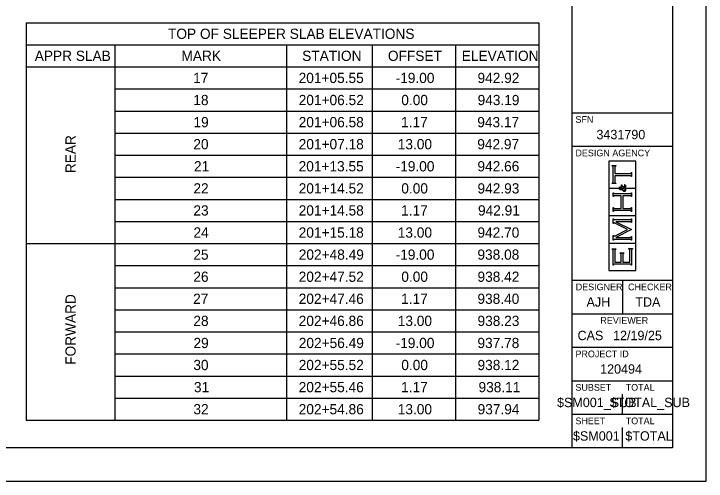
# Model space of a CAD drawing. Extents: x 0 to 34, y 0 to 22.
# Drawn here: x 23.67 to 34, y 0 to 6.98 of the extents above; entities that cross this region are included whole.
import ezdxf

# ---------------------------------------------------------------- set-up
doc = ezdxf.new("R2010")
doc.units = 0
for name, color, linetype in [('BR_P_Gen_Text', 7, 'Continuous'), ('SH_Border', 7, 'Continuous'), ('SH_Cut_Line', 7, 'Continuous'), ('SH_Data', 7, 'Continuous')]:
    doc.layers.add(name, color=color, linetype=linetype)

msp = doc.modelspace()

# ---------------------------------------------------------------- linework, layer by layer
at = {"layer": 'BR_P_Gen_Text'}
for p, q in [((23.857, 6.844), (31.504, 6.844)), ((23.857, 6.844), (23.857, 0.91)), ((31.504, 6.844), (31.504, 0.91)), ((23.857, 6.515), (31.504, 6.515)), ((25.176, 6.515), (25.176, 0.91)), ((27.738, 6.515), (27.738, 0.91)), ((29.019, 6.515), (29.019, 0.91)), ((30.261, 6.515), (30.261, 0.91)), ((23.857, 6.185), (31.504, 6.185)), ((25.176, 5.855), (31.504, 5.855)), ((25.176, 5.526), (31.504, 5.526)), ((25.176, 5.196), (31.504, 5.196)), ((25.176, 4.866), (31.504, 4.866)), ((25.176, 4.537), (31.504, 4.537)), ((25.176, 4.207), (31.504, 4.207)), ((25.176, 3.877), (31.504, 3.877)), ((23.857, 3.547), (31.504, 3.547)), ((25.176, 3.218), (31.504, 3.218)), ((25.176, 2.888), (31.504, 2.888)), ((25.176, 2.558), (31.504, 2.558)), ((25.176, 2.229), (31.504, 2.229)), ((25.176, 1.899), (31.504, 1.899)), ((25.176, 1.569), (31.504, 1.569)), ((25.176, 1.239), (31.504, 1.239)), ((23.857, 0.91), (31.504, 0.91))]:
    msp.add_line(p, q, dxfattribs=at)
at = {"layer": 'SH_Border'}
for p, q in [((32, 0.5), (32, 21.5)), ((32, 5.5), (33.5, 5.5)), ((32, 5), (33.5, 5)), ((32, 3), (33.5, 3)), ((32.75, 3), (32.75, 2.5)), ((32, 2.5), (33.5, 2.5)), ((32, 2), (33.5, 2)), ((32, 1.5), (33.5, 1.5)), ((32, 1), (33.5, 1))]:
    msp.add_line(p, q, dxfattribs=at)
msp.add_lwpolyline([(1.5, 21.5), (33.5, 21.5), (33.5, 0.5), (1.5, 0.5)], close=True, dxfattribs=at)
at = {"layer": 'SH_Cut_Line'}
msp.add_lwpolyline([(0, 0), (34, 0), (34, 22), (0, 22)], close=True, dxfattribs=at)
at = {"layer": 'SH_Data'}
for p, q in [((32.952, 4.779), (32.547, 4.779)), ((32.547, 4.779), (32.547, 4.375)), ((32.952, 4.375), (32.952, 4.779)), ((32.598, 4.704), (32.598, 4.711)), ((32.598, 4.711), (32.65, 4.711)), ((32.603, 4.703), (32.598, 4.704)), ((32.606, 4.701), (32.603, 4.703)), ((32.608, 4.699), (32.606, 4.701)), ((32.61, 4.696), (32.608, 4.699)), ((32.611, 4.692), (32.61, 4.696)), ((32.611, 4.687), (32.611, 4.692)), ((32.611, 4.468), (32.611, 4.687)), ((32.638, 4.696), (32.637, 4.692)), ((32.637, 4.692), (32.637, 4.687)), ((32.637, 4.687), (32.637, 4.593)), ((32.64, 4.699), (32.638, 4.696)), ((32.642, 4.701), (32.64, 4.699)), ((32.645, 4.703), (32.642, 4.701)), ((32.65, 4.704), (32.645, 4.703)), ((32.65, 4.711), (32.65, 4.704)), ((32.637, 4.593), (32.864, 4.593)), ((32.864, 4.561), (32.637, 4.561)), ((32.637, 4.561), (32.637, 4.468)), ((32.864, 4.593), (32.869, 4.593)), ((32.87, 4.561), (32.864, 4.561)), ((32.869, 4.593), (32.873, 4.594)), ((32.874, 4.56), (32.87, 4.561)), ((32.873, 4.594), (32.876, 4.596)), ((32.876, 4.559), (32.874, 4.56)), ((32.876, 4.596), (32.878, 4.597)), ((32.878, 4.557), (32.876, 4.559)), ((32.878, 4.597), (32.88, 4.601)), ((32.88, 4.553), (32.878, 4.557)), ((32.88, 4.601), (32.881, 4.606)), ((32.881, 4.548), (32.88, 4.553)), ((32.881, 4.606), (32.888, 4.606)), ((32.888, 4.548), (32.881, 4.548)), ((32.888, 4.606), (32.888, 4.548)), ((32.598, 4.45), (32.603, 4.451)), ((32.598, 4.444), (32.598, 4.45)), ((32.65, 4.444), (32.598, 4.444)), ((32.603, 4.451), (32.606, 4.453)), ((32.606, 4.453), (32.608, 4.455)), ((32.608, 4.455), (32.61, 4.458)), ((32.61, 4.458), (32.611, 4.462)), ((32.611, 4.462), (32.611, 4.468)), ((32.637, 4.468), (32.637, 4.462)), ((32.637, 4.462), (32.638, 4.458)), ((32.638, 4.458), (32.64, 4.455)), ((32.64, 4.455), (32.642, 4.453)), ((32.642, 4.453), (32.645, 4.451)), ((32.645, 4.451), (32.65, 4.45)), ((32.65, 4.45), (32.65, 4.444)), ((32.547, 4.375), (32.696, 4.375)), ((32.696, 4.369), (32.547, 4.369)), ((32.547, 4.369), (32.547, 3.965)), ((32.696, 4.375), (32.696, 4.369)), ((32.703, 4.379), (32.705, 4.383)), ((32.703, 4.373), (32.703, 4.379)), ((32.703, 4.368), (32.703, 4.373)), ((32.705, 4.363), (32.703, 4.368)), ((32.705, 4.383), (32.708, 4.387)), ((32.708, 4.358), (32.705, 4.363)), ((32.708, 4.387), (32.711, 4.39)), ((32.709, 4.379), (32.708, 4.376)), ((32.708, 4.376), (32.708, 4.373)), ((32.708, 4.373), (32.708, 4.369)), ((32.708, 4.369), (32.71, 4.366)), ((32.712, 4.353), (32.708, 4.358)), ((32.712, 4.381), (32.709, 4.379)), ((32.71, 4.366), (32.712, 4.364)), ((32.711, 4.39), (32.715, 4.392)), ((32.714, 4.383), (32.712, 4.381)), ((32.712, 4.364), (32.715, 4.362)), ((32.718, 4.35), (32.712, 4.353)), ((32.716, 4.384), (32.714, 4.383)), ((32.715, 4.392), (32.72, 4.392)), ((32.715, 4.362), (32.718, 4.361)), ((32.72, 4.384), (32.716, 4.384)), ((32.718, 4.361), (32.721, 4.361)), ((32.726, 4.35), (32.718, 4.35)), ((32.72, 4.392), (32.725, 4.392)), ((32.724, 4.384), (32.72, 4.384)), ((32.721, 4.361), (32.723, 4.361)), ((32.723, 4.361), (32.725, 4.362)), ((32.728, 4.382), (32.724, 4.384)), ((32.725, 4.392), (32.729, 4.39)), ((32.725, 4.362), (32.728, 4.362)), ((32.729, 4.35), (32.726, 4.35)), ((32.731, 4.38), (32.728, 4.382)), ((32.728, 4.362), (32.731, 4.363)), ((32.729, 4.39), (32.732, 4.387)), ((32.731, 4.35), (32.729, 4.35)), ((32.734, 4.377), (32.731, 4.38)), ((32.731, 4.363), (32.735, 4.365)), ((32.734, 4.351), (32.731, 4.35)), ((32.732, 4.387), (32.736, 4.383)), ((32.737, 4.372), (32.734, 4.377)), ((32.737, 4.352), (32.734, 4.351)), ((32.735, 4.365), (32.74, 4.367)), ((32.736, 4.383), (32.74, 4.378)), ((32.74, 4.367), (32.737, 4.372)), ((32.741, 4.353), (32.737, 4.352)), ((32.738, 4.393), (32.738, 4.422)), ((32.738, 4.422), (32.741, 4.422)), ((32.741, 4.393), (32.738, 4.393)), ((32.74, 4.378), (32.744, 4.369)), ((32.741, 4.422), (32.741, 4.418)), ((32.741, 4.418), (32.742, 4.415)), ((32.742, 4.396), (32.741, 4.395)), ((32.741, 4.395), (32.741, 4.393)), ((32.746, 4.355), (32.741, 4.353)), ((32.742, 4.415), (32.743, 4.413)), ((32.743, 4.397), (32.742, 4.396)), ((32.743, 4.413), (32.745, 4.411)), ((32.745, 4.399), (32.743, 4.397)), ((32.744, 4.369), (32.754, 4.375)), ((32.745, 4.411), (32.749, 4.408)), ((32.746, 4.399), (32.745, 4.399)), ((32.748, 4.399), (32.746, 4.399)), ((32.752, 4.344), (32.746, 4.355)), ((32.755, 4.399), (32.748, 4.399)), ((32.749, 4.408), (32.756, 4.404)), ((32.756, 4.36), (32.751, 4.357)), ((32.751, 4.357), (32.754, 4.352)), ((32.757, 4.337), (32.752, 4.344)), ((32.754, 4.375), (32.764, 4.381)), ((32.754, 4.352), (32.757, 4.348)), ((32.763, 4.395), (32.755, 4.399)), ((32.756, 4.404), (32.763, 4.4)), ((32.761, 4.363), (32.756, 4.36)), ((32.757, 4.348), (32.761, 4.345)), ((32.764, 4.365), (32.761, 4.363)), ((32.761, 4.345), (32.765, 4.343)), ((32.763, 4.4), (32.77, 4.396)), ((32.772, 4.387), (32.763, 4.395)), ((32.764, 4.381), (32.772, 4.387)), ((32.768, 4.367), (32.764, 4.365)), ((32.765, 4.343), (32.769, 4.341)), ((32.774, 4.372), (32.768, 4.367)), ((32.769, 4.341), (32.773, 4.341)), ((32.77, 4.396), (32.776, 4.391)), ((32.773, 4.341), (32.778, 4.341)), ((32.782, 4.378), (32.774, 4.372)), ((32.776, 4.391), (32.781, 4.395)), ((32.778, 4.341), (32.782, 4.343)), ((32.779, 4.423), (32.781, 4.426)), ((32.782, 4.422), (32.779, 4.423)), ((32.781, 4.426), (32.787, 4.424)), ((32.781, 4.395), (32.784, 4.398)), ((32.785, 4.421), (32.782, 4.422)), ((32.786, 4.373), (32.782, 4.378)), ((32.782, 4.343), (32.786, 4.346)), ((32.784, 4.398), (32.786, 4.401)), ((32.786, 4.419), (32.785, 4.421)), ((32.788, 4.417), (32.786, 4.419)), ((32.786, 4.401), (32.788, 4.404)), ((32.791, 4.386), (32.786, 4.381)), ((32.786, 4.381), (32.791, 4.376)), ((32.788, 4.369), (32.786, 4.373)), ((32.786, 4.346), (32.789, 4.349)), ((32.787, 4.424), (32.792, 4.421)), ((32.789, 4.414), (32.788, 4.417)), ((32.788, 4.404), (32.789, 4.408)), ((32.79, 4.367), (32.788, 4.369)), ((32.789, 4.411), (32.789, 4.414)), ((32.789, 4.408), (32.789, 4.411)), ((32.789, 4.349), (32.791, 4.353)), ((32.791, 4.364), (32.79, 4.367)), ((32.794, 4.39), (32.791, 4.386)), ((32.791, 4.376), (32.795, 4.37)), ((32.791, 4.361), (32.791, 4.364)), ((32.791, 4.359), (32.791, 4.361)), ((32.791, 4.353), (32.791, 4.359)), ((32.792, 4.421), (32.795, 4.418)), ((32.796, 4.394), (32.794, 4.39)), ((32.795, 4.418), (32.798, 4.414)), ((32.795, 4.37), (32.797, 4.366)), ((32.798, 4.397), (32.796, 4.394)), ((32.797, 4.366), (32.798, 4.361)), ((32.799, 4.344), (32.797, 4.338)), ((32.798, 4.414), (32.799, 4.41)), ((32.799, 4.401), (32.798, 4.397)), ((32.798, 4.361), (32.799, 4.357)), ((32.799, 4.41), (32.799, 4.405)), ((32.799, 4.405), (32.799, 4.401)), ((32.803, 4.369), (32.799, 4.375)), ((32.799, 4.375), (32.952, 4.375)), ((32.799, 4.357), (32.799, 4.352)), ((32.799, 4.352), (32.799, 4.344)), ((32.952, 4.369), (32.803, 4.369)), ((32.952, 3.965), (32.952, 4.369)), ((32.611, 4.249), (32.611, 4.307)), ((32.611, 4.307), (32.617, 4.307)), ((32.617, 4.249), (32.611, 4.249)), ((32.617, 4.307), (32.619, 4.302)), ((32.618, 4.254), (32.617, 4.249)), ((32.62, 4.258), (32.618, 4.254)), ((32.619, 4.302), (32.62, 4.298)), ((32.62, 4.298), (32.623, 4.297)), ((32.623, 4.26), (32.62, 4.258)), ((32.623, 4.297), (32.625, 4.295)), ((32.625, 4.261), (32.623, 4.26)), ((32.625, 4.295), (32.629, 4.294)), ((32.629, 4.262), (32.625, 4.261)), ((32.629, 4.294), (32.635, 4.294)), ((32.635, 4.262), (32.629, 4.262)), ((32.635, 4.294), (32.864, 4.294)), ((32.732, 4.262), (32.635, 4.262)), ((32.732, 4.072), (32.732, 4.262)), ((32.763, 4.333), (32.757, 4.337)), ((32.864, 4.262), (32.759, 4.262)), ((32.759, 4.262), (32.759, 4.072)), ((32.768, 4.329), (32.763, 4.333)), ((32.774, 4.327), (32.768, 4.329)), ((32.779, 4.327), (32.774, 4.327)), ((32.785, 4.327), (32.779, 4.327)), ((32.79, 4.329), (32.785, 4.327)), ((32.793, 4.334), (32.79, 4.329)), ((32.797, 4.338), (32.793, 4.334)), ((32.864, 4.294), (32.869, 4.294)), ((32.87, 4.262), (32.864, 4.262)), ((32.869, 4.294), (32.873, 4.295)), ((32.874, 4.261), (32.87, 4.262)), ((32.873, 4.295), (32.876, 4.297)), ((32.876, 4.26), (32.874, 4.261)), ((32.876, 4.297), (32.878, 4.298)), ((32.878, 4.258), (32.876, 4.26)), ((32.878, 4.298), (32.88, 4.302)), ((32.88, 4.254), (32.878, 4.258)), ((32.88, 4.302), (32.881, 4.307)), ((32.881, 4.249), (32.88, 4.254)), ((32.881, 4.307), (32.888, 4.307)), ((32.888, 4.249), (32.881, 4.249)), ((32.888, 4.307), (32.888, 4.249)), ((32.611, 4.027), (32.611, 4.085)), ((32.611, 4.085), (32.617, 4.085)), ((32.617, 4.085), (32.619, 4.08)), ((32.618, 4.032), (32.617, 4.027)), ((32.62, 4.036), (32.618, 4.032)), ((32.619, 4.08), (32.62, 4.076)), ((32.62, 4.076), (32.623, 4.074)), ((32.623, 4.037), (32.62, 4.036)), ((32.623, 4.074), (32.625, 4.073)), ((32.625, 4.039), (32.623, 4.037)), ((32.625, 4.073), (32.629, 4.072)), ((32.629, 4.04), (32.625, 4.039)), ((32.629, 4.072), (32.635, 4.072)), ((32.635, 4.04), (32.629, 4.04)), ((32.635, 4.072), (32.732, 4.072)), ((32.864, 4.04), (32.635, 4.04)), ((32.759, 4.072), (32.864, 4.072)), ((32.864, 4.072), (32.87, 4.072)), ((32.87, 4.04), (32.864, 4.04)), ((32.87, 4.072), (32.874, 4.073)), ((32.874, 4.039), (32.87, 4.04)), ((32.874, 4.073), (32.876, 4.074)), ((32.876, 4.038), (32.874, 4.039)), ((32.876, 4.074), (32.878, 4.076)), ((32.878, 4.036), (32.876, 4.038)), ((32.878, 4.076), (32.88, 4.08)), ((32.88, 4.032), (32.878, 4.036)), ((32.88, 4.08), (32.881, 4.085)), ((32.881, 4.027), (32.88, 4.032)), ((32.881, 4.085), (32.888, 4.085)), ((32.888, 4.085), (32.888, 4.027)), ((32.547, 3.965), (32.952, 3.965)), ((32.952, 3.959), (32.547, 3.959)), ((32.547, 3.959), (32.547, 3.555)), ((32.617, 4.027), (32.611, 4.027)), ((32.75, 4), (32.75, 4)), ((32.888, 4.027), (32.881, 4.027)), ((32.952, 3.555), (32.952, 3.959)), ((32.611, 3.845), (32.611, 3.918)), ((32.611, 3.918), (32.617, 3.918)), ((32.617, 3.845), (32.611, 3.845)), ((32.617, 3.918), (32.619, 3.912)), ((32.62, 3.852), (32.617, 3.845)), ((32.619, 3.912), (32.62, 3.909)), ((32.62, 3.909), (32.623, 3.907)), ((32.622, 3.855), (32.62, 3.852)), ((32.626, 3.855), (32.622, 3.855)), ((32.623, 3.907), (32.625, 3.905)), ((32.625, 3.905), (32.629, 3.905)), ((32.629, 3.855), (32.626, 3.855)), ((32.629, 3.905), (32.635, 3.905)), ((32.633, 3.853), (32.629, 3.855)), ((32.64, 3.85), (32.633, 3.853)), ((32.635, 3.905), (32.864, 3.905)), ((32.825, 3.757), (32.64, 3.85)), ((32.864, 3.873), (32.654, 3.873)), ((32.654, 3.873), (32.888, 3.755)), ((32.864, 3.905), (32.869, 3.905)), ((32.87, 3.873), (32.864, 3.873)), ((32.869, 3.905), (32.873, 3.905)), ((32.874, 3.872), (32.87, 3.873)), ((32.873, 3.905), (32.876, 3.907)), ((32.876, 3.87), (32.874, 3.872)), ((32.876, 3.907), (32.878, 3.909)), ((32.878, 3.869), (32.876, 3.87)), ((32.878, 3.909), (32.88, 3.912)), ((32.88, 3.865), (32.878, 3.869)), ((32.88, 3.912), (32.881, 3.918)), ((32.881, 3.86), (32.88, 3.865)), ((32.881, 3.918), (32.888, 3.918)), ((32.888, 3.86), (32.881, 3.86)), ((32.888, 3.918), (32.888, 3.86)), ((32.641, 3.665), (32.825, 3.757)), ((32.888, 3.755), (32.654, 3.638)), ((32.611, 3.596), (32.611, 3.668)), ((32.611, 3.668), (32.617, 3.668)), ((32.617, 3.668), (32.62, 3.662)), ((32.62, 3.662), (32.622, 3.658)), ((32.622, 3.658), (32.626, 3.658)), ((32.626, 3.658), (32.627, 3.658)), ((32.627, 3.658), (32.633, 3.661)), ((32.633, 3.661), (32.641, 3.665)), ((32.654, 3.638), (32.864, 3.638)), ((32.864, 3.638), (32.869, 3.638)), ((32.869, 3.638), (32.873, 3.639)), ((32.873, 3.639), (32.876, 3.641)), ((32.876, 3.641), (32.878, 3.643)), ((32.878, 3.643), (32.88, 3.646)), ((32.88, 3.646), (32.881, 3.651)), ((32.881, 3.651), (32.888, 3.651)), ((32.888, 3.651), (32.888, 3.596)), ((32.547, 3.555), (32.952, 3.555)), ((32.952, 3.549), (32.547, 3.549)), ((32.547, 3.549), (32.547, 3.145)), ((32.617, 3.596), (32.611, 3.596)), ((32.618, 3.602), (32.617, 3.596)), ((32.62, 3.605), (32.618, 3.602)), ((32.623, 3.607), (32.62, 3.605)), ((32.625, 3.609), (32.623, 3.607)), ((32.629, 3.609), (32.625, 3.609)), ((32.635, 3.609), (32.629, 3.609)), ((32.864, 3.609), (32.635, 3.609)), ((32.87, 3.609), (32.864, 3.609)), ((32.874, 3.609), (32.87, 3.609)), ((32.876, 3.607), (32.874, 3.609)), ((32.878, 3.605), (32.876, 3.607)), ((32.88, 3.602), (32.878, 3.605)), ((32.881, 3.596), (32.88, 3.602)), ((32.888, 3.596), (32.881, 3.596)), ((32.952, 3.145), (32.952, 3.549)), ((32.598, 3.462), (32.598, 3.469)), ((32.598, 3.469), (32.65, 3.469)), ((32.603, 3.461), (32.598, 3.462)), ((32.606, 3.459), (32.603, 3.461)), ((32.608, 3.457), (32.606, 3.459)), ((32.61, 3.455), (32.608, 3.457)), ((32.611, 3.451), (32.61, 3.455)), ((32.611, 3.445), (32.611, 3.451)), ((32.611, 3.225), (32.611, 3.445)), ((32.64, 3.457), (32.638, 3.455)), ((32.638, 3.455), (32.638, 3.451)), ((32.638, 3.451), (32.638, 3.445)), ((32.638, 3.445), (32.638, 3.27)), ((32.642, 3.459), (32.64, 3.457)), ((32.645, 3.461), (32.642, 3.459)), ((32.65, 3.462), (32.645, 3.461)), ((32.65, 3.469), (32.65, 3.462)), ((32.848, 3.465), (32.848, 3.472)), ((32.848, 3.472), (32.901, 3.472)), ((32.853, 3.464), (32.848, 3.465)), ((32.857, 3.462), (32.853, 3.464)), ((32.859, 3.46), (32.857, 3.462)), ((32.86, 3.458), (32.859, 3.46)), ((32.861, 3.453), (32.86, 3.458)), ((32.861, 3.448), (32.861, 3.453)), ((32.861, 3.27), (32.861, 3.448)), ((32.889, 3.457), (32.888, 3.453)), ((32.888, 3.453), (32.888, 3.448)), ((32.888, 3.448), (32.888, 3.225)), ((32.891, 3.46), (32.889, 3.457)), ((32.892, 3.462), (32.891, 3.46)), ((32.896, 3.464), (32.892, 3.462)), ((32.901, 3.465), (32.896, 3.464)), ((32.901, 3.472), (32.901, 3.465)), ((32.719, 3.402), (32.719, 3.408)), ((32.719, 3.408), (32.772, 3.408)), ((32.724, 3.401), (32.719, 3.402)), ((32.728, 3.399), (32.724, 3.401)), ((32.729, 3.396), (32.728, 3.399)), ((32.731, 3.394), (32.729, 3.396)), ((32.732, 3.39), (32.731, 3.394)), ((32.732, 3.384), (32.732, 3.39)), ((32.732, 3.27), (32.732, 3.384)), ((32.76, 3.394), (32.759, 3.39)), ((32.759, 3.39), (32.759, 3.384)), ((32.759, 3.384), (32.759, 3.27)), ((32.761, 3.396), (32.76, 3.394)), ((32.763, 3.399), (32.761, 3.396)), ((32.767, 3.401), (32.763, 3.399)), ((32.772, 3.402), (32.767, 3.401)), ((32.772, 3.408), (32.772, 3.402)), ((32.617, 3.225), (32.611, 3.225)), ((32.619, 3.23), (32.617, 3.225)), ((32.62, 3.234), (32.619, 3.23)), ((32.623, 3.235), (32.62, 3.234)), ((32.625, 3.237), (32.623, 3.235)), ((32.629, 3.238), (32.625, 3.237)), ((32.635, 3.238), (32.629, 3.238)), ((32.864, 3.238), (32.635, 3.238)), ((32.638, 3.27), (32.732, 3.27)), ((32.759, 3.27), (32.861, 3.27)), ((32.87, 3.238), (32.864, 3.238)), ((32.874, 3.237), (32.87, 3.238)), ((32.876, 3.235), (32.874, 3.237)), ((32.878, 3.234), (32.876, 3.235)), ((32.88, 3.23), (32.878, 3.234)), ((32.881, 3.225), (32.88, 3.23)), ((32.888, 3.225), (32.881, 3.225)), ((32.547, 3.145), (32.952, 3.145)), ((32.75, 1), (32.75, 1.3)), ((32.75, 0.5), (32.75, 0.8)), ((32.375, 0.675), (32.375, 0.675))]:
    msp.add_line(p, q, dxfattribs=at)

# ---------------------------------------------------------------- texts
at = {"layer": 'BR_P_Gen_Text'}
for s, height, p in [('TOP OF SLEEPER SLAB ELEVATIONS', 0.15273, (25.971, 6.603)), ('APPR SLAB', 0.1527, (23.983, 6.274)), ('MARK', 0.1527, (26.172, 6.274)), ('STATION', 0.1527, (27.973, 6.274)), ('OFFSET', 0.1527, (29.252, 6.274)), ('ELEVATION', 0.1527, (30.353, 6.274)), ('17', 0.1527, (26.346, 5.944)), ('201+05.55', 0.1527, (27.92, 5.944)), ('-19.00', 0.1527, (29.367, 5.944)), ('942.92', 0.1527, (30.589, 5.944)), ('18', 0.1527, (26.349, 5.614)), ('201+06.52', 0.1527, (27.921, 5.614)), ('0.00', 0.1527, (29.452, 5.614)), ('943.19', 0.1527, (30.59, 5.614)), ('19', 0.1527, (26.351, 5.284)), ('201+06.58', 0.1527, (27.921, 5.284)), ('1.17', 0.1527, (29.449, 5.284)), ('943.17', 0.1527, (30.585, 5.284)), ('20', 0.1527, (26.349, 4.955)), ('201+07.18', 0.1527, (27.921, 4.955)), ('13.00', 0.1527, (29.399, 4.955)), ('942.97', 0.1527, (30.585, 4.955)), ('21', 0.1527, (26.358, 4.625)), ('201+13.55', 0.1527, (27.92, 4.625)), ('-19.00', 0.1527, (29.367, 4.625)), ('942.66', 0.1527, (30.588, 4.625)), ('22', 0.1527, (26.35, 4.295)), ('201+14.52', 0.1527, (27.921, 4.295)), ('0.00', 0.1527, (29.452, 4.295)), ('942.93', 0.1527, (30.589, 4.295)), ('23', 0.1527, (26.35, 3.966)), ('201+14.58', 0.1527, (27.921, 3.966)), ('1.17', 0.1527, (29.449, 3.966)), ('942.91', 0.1527, (30.596, 3.966)), ('24', 0.1527, (26.351, 3.636)), ('201+15.18', 0.1527, (27.921, 3.636)), ('13.00', 0.1527, (29.399, 3.636)), ('942.70', 0.1527, (30.588, 3.636)), ('25', 0.1527, (26.349, 3.306)), ('202+48.49', 0.1527, (27.922, 3.306)), ('-19.00', 0.1527, (29.367, 3.306)), ('938.08', 0.1527, (30.588, 3.306)), ('26', 0.1527, (26.349, 2.976)), ('202+47.52', 0.1527, (27.921, 2.976)), ('0.00', 0.1527, (29.452, 2.976)), ('938.42', 0.1527, (30.589, 2.976)), ('27', 0.1527, (26.346, 2.647)), ('202+47.46', 0.1527, (27.921, 2.647)), ('1.17', 0.1527, (29.449, 2.647)), ('938.40', 0.1527, (30.588, 2.647)), ('28', 0.1527, (26.349, 2.317)), ('202+46.86', 0.1527, (27.921, 2.317)), ('13.00', 0.1527, (29.399, 2.317)), ('938.23', 0.1527, (30.589, 2.317)), ('29', 0.1527, (26.351, 1.987)), ('202+56.49', 0.1527, (27.922, 1.987)), ('-19.00', 0.1527, (29.367, 1.987)), ('937.78', 0.1527, (30.588, 1.987)), ('30', 0.1527, (26.349, 1.658)), ('202+55.52', 0.1527, (27.921, 1.658)), ('0.00', 0.1527, (29.452, 1.658)), ('938.12', 0.1527, (30.589, 1.658)), ('31', 0.1527, (26.358, 1.328)), ('202+55.46', 0.1527, (27.921, 1.328)), ('1.17', 0.1527, (29.449, 1.328)), ('938.11', 0.1527, (30.604, 1.328)), ('32', 0.1527, (26.35, 0.998)), ('202+54.86', 0.1527, (27.921, 0.998)), ('13.00', 0.1527, (29.399, 0.998)), ('937.94', 0.1527, (30.59, 0.998))]:
    msp.add_text(s, height=height, dxfattribs=at).set_placement(p)
for s, p in [('REAR', (24.593, 4.599)), ('FORWARD', (24.593, 1.737))]:
    msp.add_text(s, height=0.1527, rotation=90, dxfattribs=at).set_placement(p)
at = {"layer": 'SH_Data'}
for s, height, p in [('SFN', 0.1, (32.05, 5.35)), ('3431790', 0.14, (32.363, 5.105)), ('DESIGN AGENCY', 0.1, (32.05, 4.85)), ('DESIGNER', 0.1, (32.054, 2.85)), ('CHECKER', 0.1, (32.835, 2.85)), ('AJH', 0.14, (32.215, 2.605)), ('TDA', 0.14, (32.943, 2.605)), ('REVIEWER', 0.1, (32.422, 2.35)), ('CAS', 0.14, (32.081, 2.105)), ('12/19/25', 0.14, (32.611, 2.105)), ('PROJECT ID', 0.1, (32.05, 1.85)), ('120494', 0.14, (32.418, 1.605)), ('SUBSET', 0.1, (32.05, 1.35)), ('TOTAL', 0.1, (32.8, 1.35)), ('$SM001_SUB', 0.14, (31.775, 1.105)), ('$TOTAL_SUB', 0.14, (32.562, 1.105)), ('SHEET', 0.1, (32.05, 0.85)), ('TOTAL', 0.1, (32.8, 0.85)), ('$SM001', 0.14, (32.013, 0.605)), ('$TOTAL', 0.14, (32.794, 0.605))]:
    msp.add_text(s, height=height, dxfattribs=at).set_placement(p)

doc.saveas('drawing.dxf')
